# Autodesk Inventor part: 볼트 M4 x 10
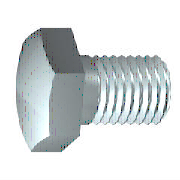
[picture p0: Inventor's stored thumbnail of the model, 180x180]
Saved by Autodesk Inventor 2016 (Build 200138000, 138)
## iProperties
Created: 2012-02
Part Number: 볼트 M4 x 10
Material: 스테인리스강
Description: 6각 머리 나사
Document SubType Name: Modeling
Standard: ISO 4017
Designer: mduedu
Standard Revision: Third edition 1999-08-15
Standards Organization: ISO
Language: ko-KR
Size Designation: M4 x 10
Categories: <MemberInstance><Categories><Category DisplayName="조임쇠" InternalName="e4da775c-781d-43d5-af7c-5136215cf5a6" Mnemonic="FSTN"><Category DisplayName="볼트" InternalN
Density: 8.08 g/cm^3
Appearance: 기본값
IsCustomPart: 0
Author: mduedu
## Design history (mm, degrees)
sketch "스케치1"
  geometry: L1 (0, 3.015)-(0, 2); L2 (1.25, 2)-(10, 2); L3 (10, 2)-(10, 0); L4 (10, 0)-(-0.4, 0); L5 (-2.48, 0)-(12.08, 0) reference; L6 (-0.4, 0)-(-0.4, 3.015); L7 (-0.4, 3.015)-(0, 3.015); L8 (1.25, 2)-(0.82, 2); L9 (0.82, 2)-(0, 2); L10 (0, -0.603)-(0, 3.618) reference
  constraints: 16 end point, 2 collinear, 2 perpendicular, 1 parallel
  dimensions: "d0" = 10 distance between parallel lines of L3 L1 (= NLG); "d1" = 8.75 distance from line of L2.start L3 (= GEL); "d2" = 4 diameter of L2 L4 (= GD); "d9" = 0.4001 distance between parallel lines of L6 L1 (computed from SD); "d10" = 6.03 diameter of L7 L4 (= SD2); "d13" = 0.42952 distance of L2.start L8.end (computed from GAL); "d14" = 4 diameter of L9 L4 (= BDM)
revolve "본체" sketch "스케치1" stored, may be unused: angle "d12" = 90 deg
sketch "스케치2"
  geometry: L1 (0, 4.041)-(3.5, 2.021); L2 (3.5, 2.021)-(3.5, -2.021); L3 (3.5, -2.021)-(0, -4.041); L4 (0, -4.041)-(-3.5, -2.021); L5 (-3.5, -2.021)-(-3.5, 2.021); L6 (-3.5, 2.021)-(0, 4.041); 2 further points
  constraints: 12 end point, 1 coincident, 1 vertical, 11 other
  dimensions: "d11" = 7 distance between parallel lines of L5 L2 (= SW)
extrude "머리" join sketch "스케치2" distance "d3" = 2.4 (= KOH - SD); taper "d4" = 0 deg
sketch "스케치4"
  geometry: L1 (-2.8, 3.5)-(-2.8, 4.041); L2 (-2.8, 4.041)-(-2.487, 4.041); L3 (-2.487, 4.041)-(-2.8, 3.5); L4 (-3.28, 0)-(0.08, 0) reference; L5 (-0.4, 4.041)-(-2.8, 4.041) reference; L6 (-2.8, 2.021)-(-2.8, 4.041) reference
  constraints: 6 end point, 2 collinear, 1 perpendicular, 1 vertical
  dimensions: "d5" = 30 deg angle of L3 L1 (= ANG1); "d19" = 7 diameter of L1.start L4 (= SW0)
revolve "모따기1" sketch "스케치4" stored, may be unused: angle "d21" = 90 deg
workplane "Work Plane1"
body "Solid1"
feature "스레드" dims "d15" = 8.75 (= GEL), "d16" = 0
chamfer "모따기2" distance "d6" = 0.42941 (= -0.5 x SPD + 0.5 x GD); stored, may be unused: second distance "d7" = 0.42952 (computed from GUL), angle "d55" = 45 deg
other parameters: "NLG" = 10 [user parameter; used in 1 equation term], "GD" = 4 (= NND) [user parameter; used in 2 equation terms], "BDM" = 4 (= NND) [user parameter; used in 1 equation term], "KOH" = 2.8 [user parameter; used in 1 equation term], "GEL" = 8.75 [user parameter; used in 2 equation terms], "SW" = 7 [user parameter; used in 2 equation terms], "SW0" = 7 (= SW) [user parameter; used in 1 equation term], "SPD" = 3.14117 (= NND - 1.2269 x PTC) [user parameter; used in 1 equation term], "SD2" = 6.03 [user parameter; used in 2 equation terms], "SD" = 0.4 [user parameter; used in 2 equation terms], "ANG1" = 30 deg [user parameter; used in 1 equation term], "GAL" = 0.42941 (= 0.61345 x PTC) [user parameter; used in 1 equation term], "GUL" = 0.42941 (= 0.61345 x PTC) [user parameter; used in 1 equation term], "d8" = 0, "RR" = 0.2 [user parameter], "d57" = 0, "d58" = 0, "TPU" = 14.28571 (computed from PTC) [user parameter], "GD1" = 3.14117 (= THREADDIA - 1.2269 x PTC) [user parameter], "THREADDIA" = 4 [user parameter; used in 1 equation term], "SDH" = 6.03 (= SD2) [user parameter], "SDHG" = 2.1 [user parameter], "TOA" = 30 deg [user parameter], "PTC" = 0.7 [user parameter; used in 5 equation terms], "NND" = 4 [user parameter; used in 3 equation terms], "E0" = 8.085 [user parameter]
